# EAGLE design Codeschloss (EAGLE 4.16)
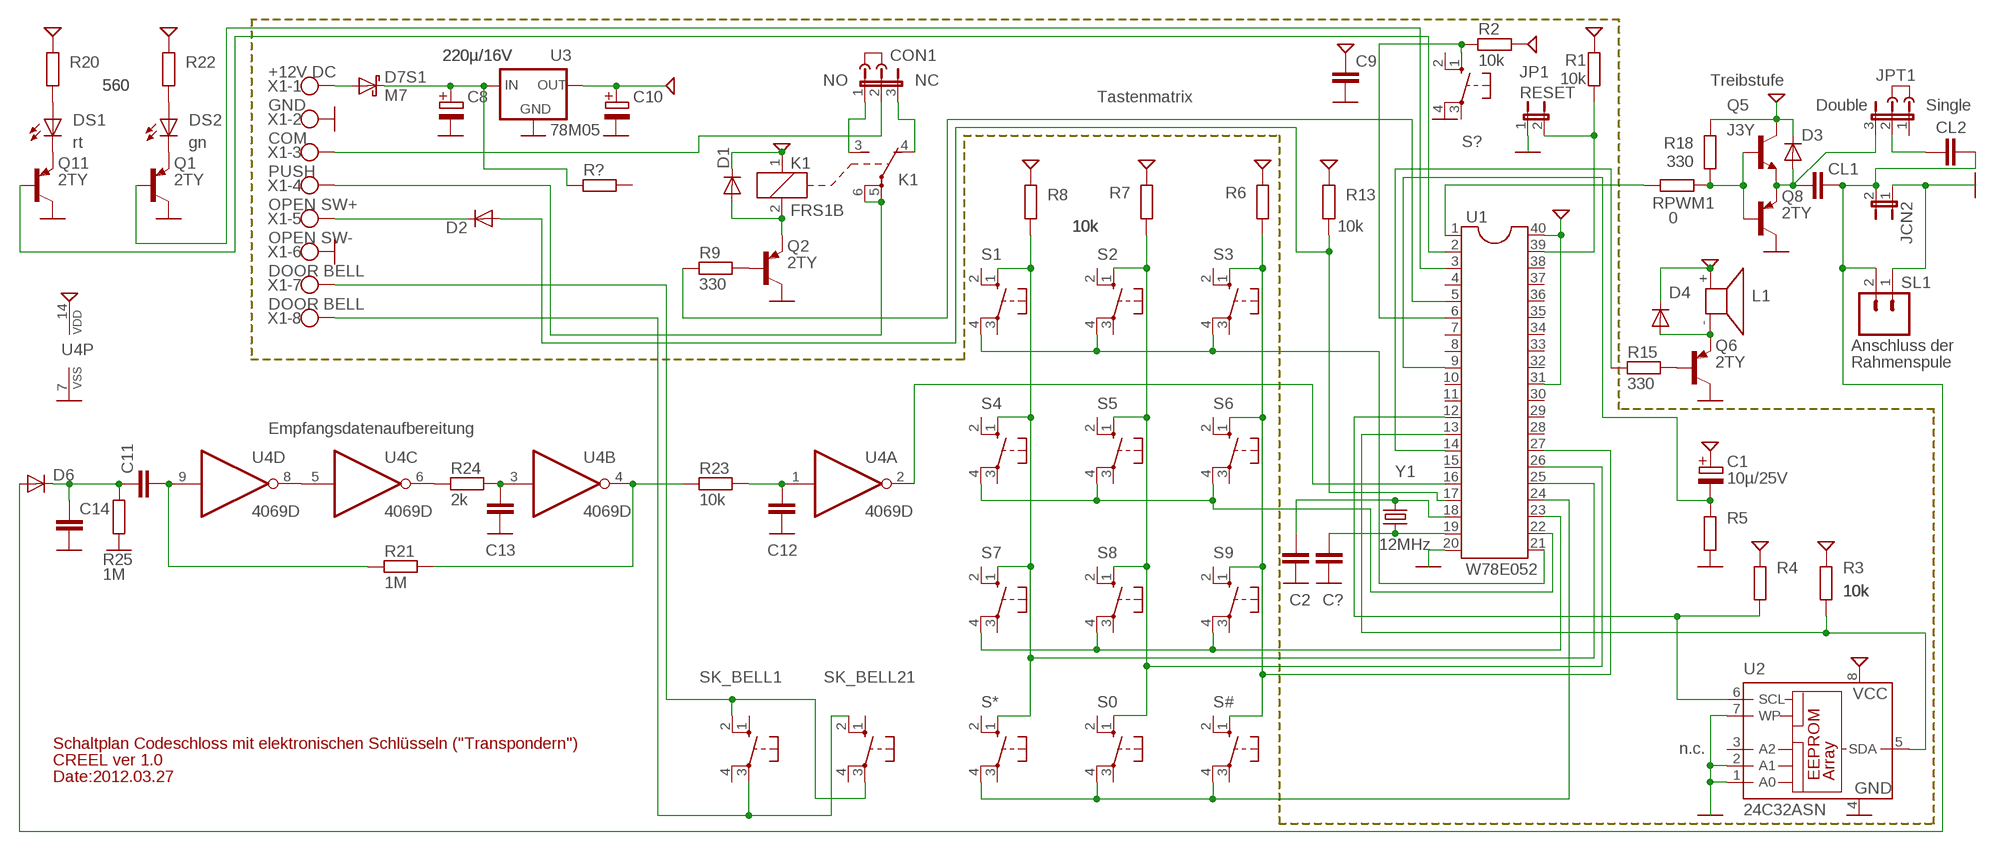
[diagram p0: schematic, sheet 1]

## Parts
C1  10µ/25V  E01-5  [E01-5]
C2  C0603  [0603]
C8  220µ/16V  E01-5  [E01-5]
C9  C0603  [0603]
C10  220µ/16V  E01-5  [E01-5]
C11  C0603  [0603]
C12  C0603  [0603]
C13  C0603  [0603]
C14  C0603  [0603]
C?  C0603  [0603]
CL1  C02  [C050-024X044]
CL2  C02  [C050-024X044]
CON1  JP2E  [JP2]
D1  D  [MINIMELF]
D2  D  [MINIMELF]
D3  D  [MINIMELF]
D4  D  [MINIMELF]
D6  D  [MINIMELF]
D7S1  M7  DSB  [SMB]
DS1  rt  LED3MM  [LED3MM]
DS2  gn  LED3MM  [LED3MM]
J1  JUMPER  [JUMP]
J2  JUMPER  [JUMP]
JCN2  JP1E  [JP1]
JP1  RESET  JP1E  [JP1]
JPT1  JP2E  [JP2]
K1  FRS1B  [FRS1B]
L1  KSS1201  [KSS1201]
Q1  2TY  PNP23BEC  [SOT23]
Q2  2TY  PNP23BEC  [SOT23]
Q5  J3Y  NPN23BEC  [SOT23]
Q6  2TY  PNP23BEC  [SOT23]
Q8  2TY  PNP23BEC  [SOT23]
Q11  2TY  PNP23BEC  [SOT23]
R1  10k  R0603  [0603]
R2  10k  R0603  [0603]
R3  10k  R0603  [0603]
R4  10k  R0603  [0603]
R5  10k  R0603  [0603]
R6  10k  R0603  [0603]
R7  10k  R0603  [0603]
R8  10k  R0603  [0603]
R9  330  R0603  [0603]
R13  10k  R0603  [0603]
R15  330  R0603  [0603]
R18  330  R0603  [0603]
R20  560  R0603  [0603]
R21  1M  R0603  [0603]
R22  560  R0603  [0603]
R23  10k  R0603  [0603]
R24  2k  R0603  [0603]
R25  1M  R0603  [0603]
R?  R0603  [0603]
RPWM1  0  R0603  [0603]
S0  10-XXSMD  [B3F-10SMD]
S1  10-XXSMD  [B3F-10SMD]
S2  10-XXSMD  [B3F-10SMD]
S3  10-XXSMD  [B3F-10SMD]
S4  10-XXSMD  [B3F-10SMD]
S5  10-XXSMD  [B3F-10SMD]
S6  10-XXSMD  [B3F-10SMD]
S7  10-XXSMD  [B3F-10SMD]
S8  10-XXSMD  [B3F-10SMD]
S9  10-XXSMD  [B3F-10SMD]
S#  10-XXSMD  [B3F-10SMD]
S*  10-XXSMD  [B3F-10SMD]
S?  10-XXSMD  [B3F-10SMD]
SK_BELL1  10-XXSMD  [B3F-10SMD]
SK_BELL21  10-XXSMD  [B3F-10SMD]
SL1  M02  [02P]
U1  W78E052  DIL40  [DIL40]
U2  24C32ASN  [SO-08]
U3  78M05  78MXXS  [78MXXS]
U4  4069D  [SO14]
X1  W237-08P  [W237-8P]
Y1  12MHz  CRYSTALS  [HC49/S]

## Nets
5P: C1.+ C9.1 C10.+ D1.K D3.K D4.K K1.1 L1.+ Q5.3(C) R1.2 R2.2 R3.2 R4.2 R6.2 R7.2 R8.2 R13.2 R18.2 R20.2 R22.2 U1.31 U1.40 U2.8(VCC) U3.OUT U4.14(P:VDD)
12P: C8.+ D7S1.1(K) R?.1 U3.IN
GND: C2.2 C8.- C9.2 C10.- C12.2 C13.2 C14.2 C?.2 JCN2.1 JP1.1 Q1.3(C) Q2.3(C) Q6.3(C) Q8.3(C) Q11.3(C) R5.1 R25.1 S?.4(P) SL1.1 U1.20 U2.1(A0) U2.2(A1) U2.4(GND) U2.7(WP) U3.GND U4.7(P:VSS) X1.2 X1.6
N$1: CL1.2 CL2.1 D6.A JCN2.2 SL1.2
N$2: CL2.2 JPT1.2
N$3: D7S1.2(A) X1.1
N$4: D1.A K1.2 Q2.2(E)
N$5: C?.1 U1.19 Y1.1
N$6: C2.1 U1.18 Y1.2
N$7: DS2.K(C) Q1.2(E)
N$8: DS1.K(C) Q11.2(E)
N$9: DS1.A R20.1
N$10: DS2.A R22.1
N$11: Q2.1(B) R9.2
N$12: R9.1 U1.5
N$13: S1.4(P) S2.4(P) S3.4(P) U1.21
N$14: R7.1 S0.1(S) S2.1(S) S5.1(S) S8.1(S) U1.26
N$15: R8.1 S1.1(S) S4.1(S) S7.1(S) S*.1(S) U1.25
N$16: R3.1 U1.13 U2.5(SDA)
N$17: R4.1 U1.12 U2.6(SCL)
N$18: S4.4(P) S5.4(P) S6.4(P) U1.22
N$19: Q11.1(B) U1.2
N$20: SK_BELL1.3(P) SK_BELL21.2(S) X1.8
N$21: Q1.1(B) U1.3
N$22: R6.1 S3.1(S) S6.1(S) S9.1(S) S#.1(S) U1.27
N$23: JP1.2 R1.1 U1.39
N$24: D4.A L1.- Q6.2(E)
N$25: S7.4(P) S8.4(P) S9.4(P) U1.23
N$26: S0.4(P) S#.4(P) S*.4(P) U1.24
N$27: Q6.1(B) R15.2
N$28: SK_BELL1.2(S) SK_BELL21.3(P) X1.7
N$29: R15.1 U1.14
N$30: D2.A R13.1 U1.17
N$31: RPWM1.1 U1.1
N$32: Q5.1(B) Q8.1(B) R18.1 RPWM1.2
N$33: CL1.1 D3.A JPT1.3 Q5.2(E) Q8.2(E)
N$34: C11.1 C14.1 D6.K R25.2
N$35: C11.2 R21.1 U4.9(D:I)
N$36: R21.2 R23.1 U4.4(B:O)
N$37: C12.1 R23.2 U4.1(A:I)
N$38: C13.1 R24.2 U4.3(B:I)
N$39: R24.1 U4.6(C:O)
N$40: U1.16 U4.2(A:O)
N$41: U4.5(C:I) U4.8(D:O)
N$42: CON1.1 K1.3(2:S)
N$43: CON1.3 K1.4(2:O)
N$44: K1.5(2:P) K1.6(2:P) X1.4
N$45: D2.K X1.5
N$46: CON1.2 X1.3
N$48: R2.1 S?.1(S) U1.6
RESET: C1.- R5.2 U1.9
Unconnected: JPT1.1 R?.2 S0.2(S) S0.3(P) S1.2(S) S1.3(P) S2.2(S) S2.3(P) S3.2(S) S3.3(P) S4.2(S) S4.3(P) S5.2(S) S5.3(P) S6.2(S) S6.3(P) S7.2(S) S7.3(P) S8.2(S) S8.3(P) S9.2(S) S9.3(P) S#.2(S) S#.3(P) S*.2(S) S*.3(P) S?.2(S) S?.3(P) SK_BELL1.1(S) SK_BELL1.4(P) SK_BELL21.1(S) SK_BELL21.4(P) U1.4 U1.7 U1.8 U1.10 U1.11 U1.15 U1.28 U1.29 U1.30 U1.32 U1.33 U1.34 U1.35 U1.36 U1.37 U1.38 U2.3(A2) U4.10(E:O) U4.11(E:I) U4.12(F:O) U4.13(F:I)

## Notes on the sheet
- +12V DC
- NO | NC | Treibstufe
- Tastenmatrix
- GND | Double | Single
- COM
- PUSH
- OPEN SW+
- OPEN SW-
- DOOR BELL
- DOOR BELL
- Anschluss der
- Rahmenspule
- Empfangsdatenaufbereitung
- Schaltplan Codeschloss mit elektronischen Schlüsseln ("Transpondern")
- n.c.
- CREEL ver 1.0
- Date:2012.03.27

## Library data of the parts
C1 C8 C10 = Ofen:E: Elektrolytkondensator
C2 C9 C11-C14 C? CL1 CL2 = Ofen:C: Kondensator
CON1 JPT1 = jumper:JP2E: JUMPER
D1-D4 D6 = Ofen:D: Diode
D7S1 = Ofen:DS: Schottky-Diode
DS1 DS2 = led:LED: LED
J1 J2 = jumper:JUMPER: JUMPER header
JCN2 JP1 = jumper:JP1E: JUMPER
K1 = Ofen:FRS1B: Relais, 1 Umschaltkontakt
L1 = buzzer:KSS1201: SPEAKER
Q1 Q2 Q6 Q8 Q11 = Ofen:PNP: PNP-Transistor Verschiedene Bauformen und Leistungen
Q5 = Ofen:NPN: NPN-Transistor Verschiedene Bauformen und Leistungen
R1-R9 R13 R15 R18 R20-R25 R? RPWM1 = Ofen:R: Widerstand
S0 S1-S9 S# S* S? SK_BELL1 SK_BELL21 = Ofen:10-XX: Drucktaster
SL1 = con-amp-quick:M02: AMP QUICK CONNECTOR
U1 = ic-package:DIL40: Dual In Line
U2 = microchip:24*: Serial EEPROM I2C
U3 = v-reg:78MXXS: VOLTAGE REGULATOR
U4 = 40xx:4069: Hex INVERTER
X1 = con-wago-508:W237-08P: WAGO SREW CLAMP
Y1 = Ofen:CRYSTAL: Quarz

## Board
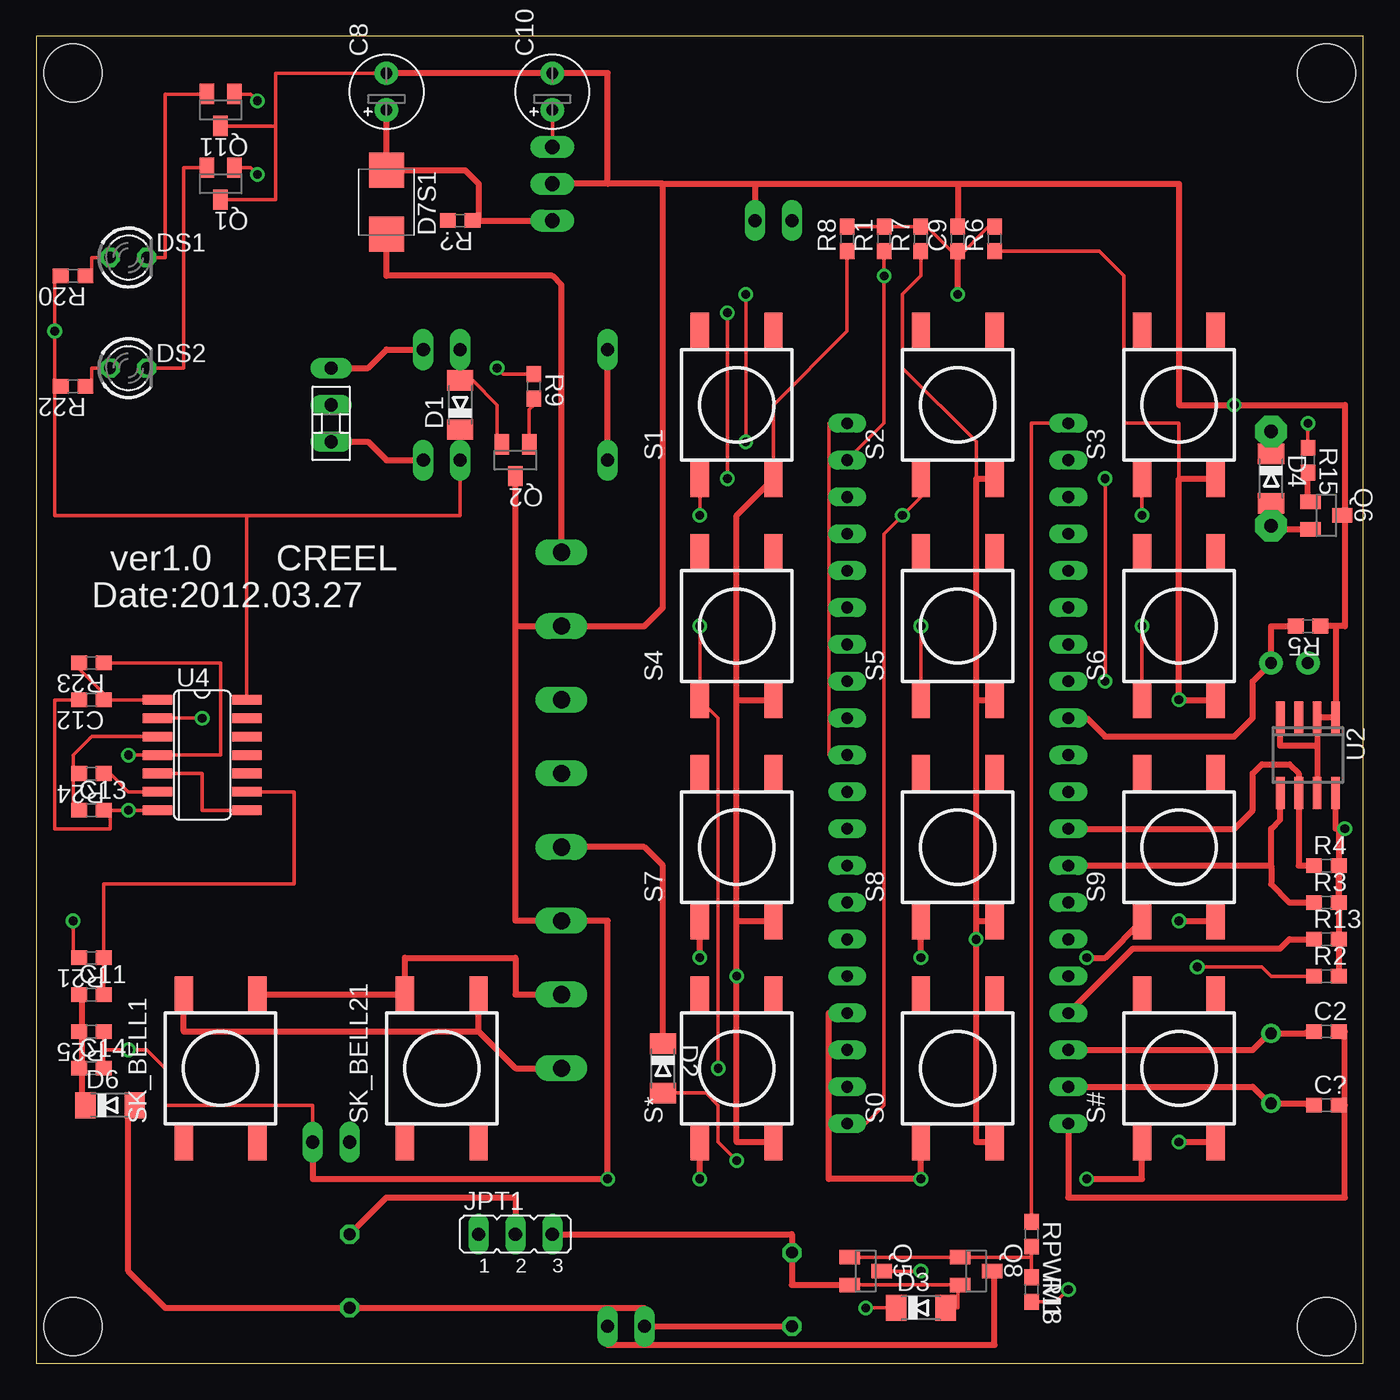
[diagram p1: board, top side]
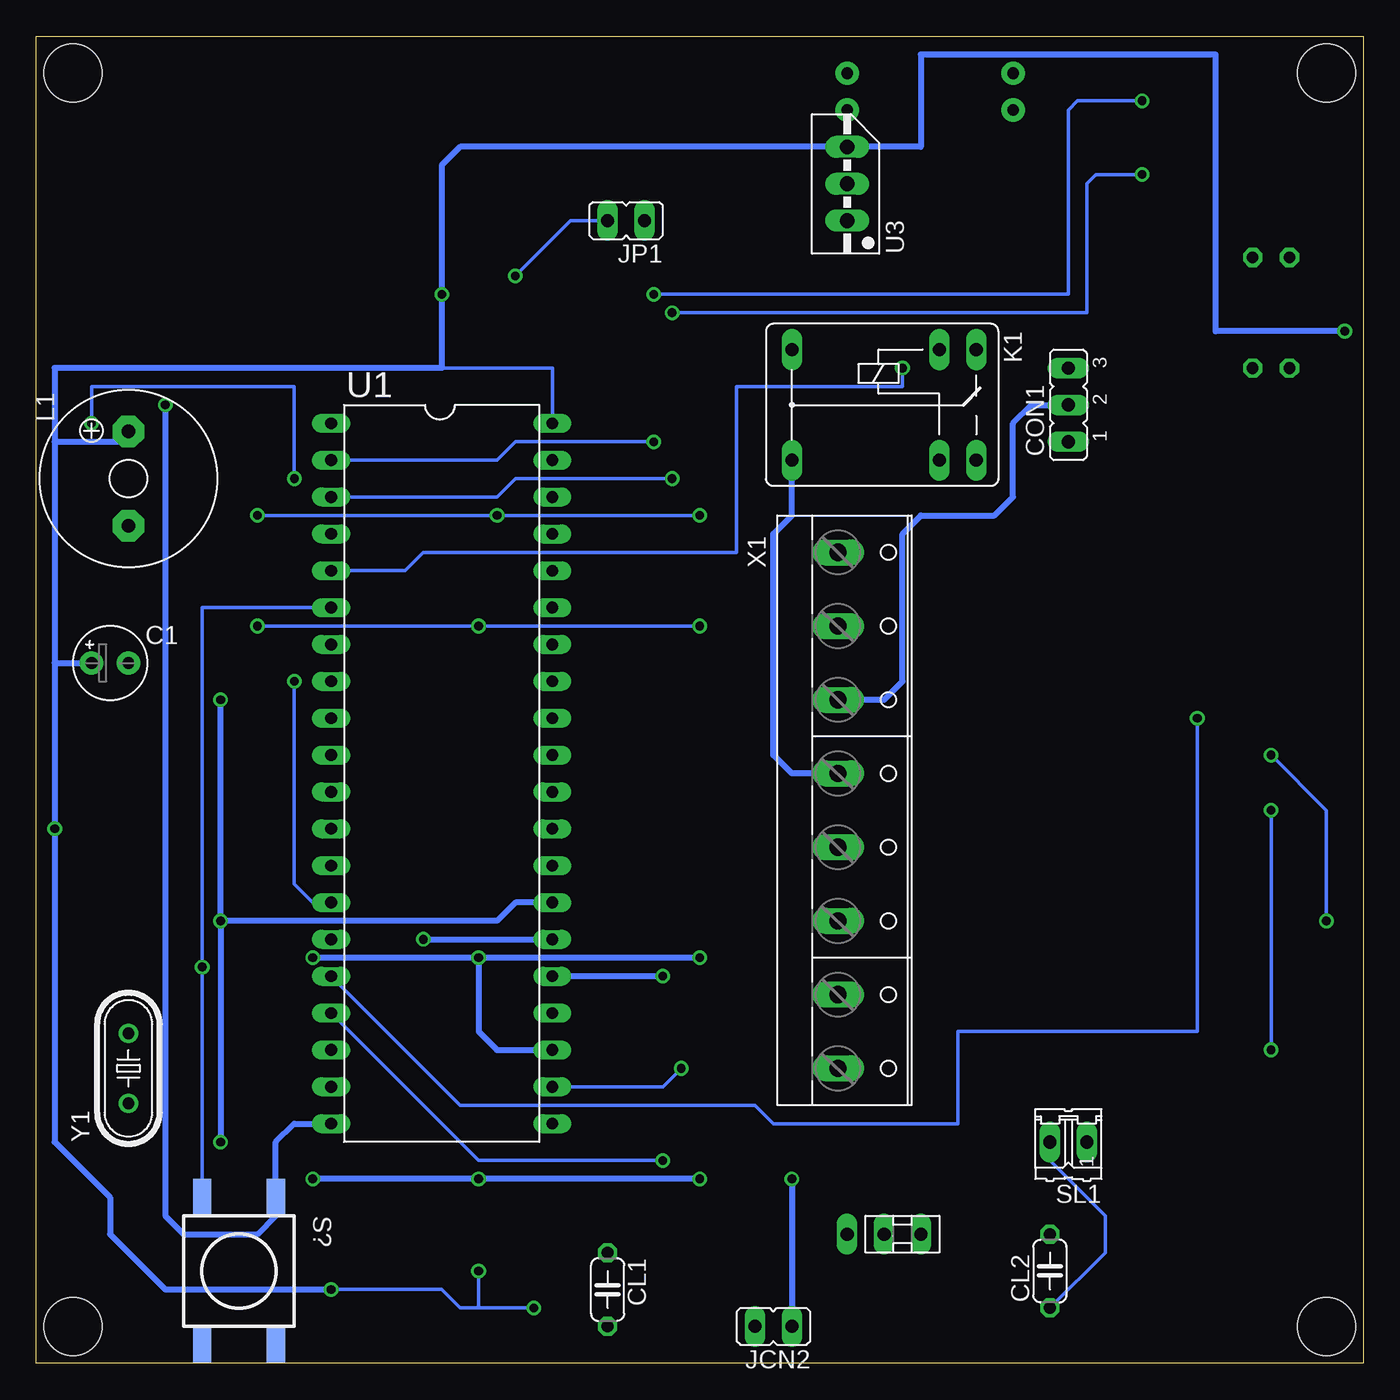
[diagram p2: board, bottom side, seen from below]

Size 91.44 x 91.44 mm. Coordinates in mm from the lower left corner, seen from the top.
Outline: 0,0 91.44,0 91.44,91.44 0,91.44 0,0
Copper layers (1+16): Top 0.035mm / dielectric 1mm / Bottom 0.035mm
Design rules "default": minimum track width 10mil, minimum drill 0.6mm, track to track 8mil, track to pad 8mil, pad to pad 8mil, via to via 8mil, smd to smd 0mil, copper to edge 0mil, drill to drill 8mil, minimum pad ring 10mil, minimum via ring 8mil, stop-mask expansion 4mil, vias tented up to drill 0mil, thermal gap 10mil
Holes 4 mm at 2.54,2.54 88.9,2.54 88.9,88.9 2.54,88.9

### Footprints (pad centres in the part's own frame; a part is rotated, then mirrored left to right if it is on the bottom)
E01-5 = drill 0.813 pad 1.6 round: + -1.27,0; - 1.27,0
0603 = smd 1.1 x 1: 1 -0.85,0; 2 0.85,0
C050-024X044 = drill 0.813 octagon: 1 -2.54,0; 2 2.54,0
JP2 = drill 0.914 long: 1 -2.54,0; 2 0,0; 3 2.54,0
MINIMELF = smd 1.4 x 1.8: A 1.7,0; K -1.7,0
SMB = smd 2.4 x 2.4: 1 -2.2,0; 2 2.2,0
LED3MM = drill 0.813 octagon: A -1.27,0; K 1.27,0
JP1 = drill 0.914 long: 1 0,-1.27; 2 0,1.27
FRS1B = drill 0.914 long: 1 0,3.81; 2 0,-3.81; 3 -2.54,3.81; 4 -2.54,-3.81; 5 10.16,3.81; 6 10.16,-3.81
KSS1201 = drill 0.914 pad 2.159 octagon: + 3.251,0; - -3.251,0
SOT23 = smd 1 x 1.4: 1 -0.95,-1.1; 2 0.95,-1.1; 3 0,1.1
B3F-10SMD = smd 2.54 x 1.27: 1 -5.08,-2.54; 2 5.08,-2.54; 3 5.08,2.54; 4 -5.08,2.54
02P = drill 0.914 long: 1 -1.27,0; 2 1.27,0
DIL40 = drill 0.813 long: 1 -24.13,-7.62; 2 -21.59,-7.62; 3 -19.05,-7.62; 4 -16.51,-7.62; 5 -13.97,-7.62; 6 -11.43,-7.62; 7 -8.89,-7.62; 8 -6.35,-7.62; 9 -3.81,-7.62; 10 -1.27,-7.62; 11 1.27,-7.62; 12 3.81,-7.62; 13 6.35,-7.62; 14 8.89,-7.62; 15 11.43,-7.62; 16 13.97,-7.62; 17 16.51,-7.62; 18 19.05,-7.62; 19 21.59,-7.62; 20 24.13,-7.62; 21 24.13,7.62; 22 21.59,7.62; 23 19.05,7.62; 24 16.51,7.62; 25 13.97,7.62; 26 11.43,7.62; 27 8.89,7.62; 28 6.35,7.62; 29 3.81,7.62; 30 1.27,7.62; 31 -1.27,7.62; 32 -3.81,7.62; 33 -6.35,7.62; 34 -8.89,7.62; 35 -11.43,7.62; 36 -13.97,7.62; 37 -16.51,7.62; 38 -19.05,7.62; 39 -21.59,7.62; 40 -24.13,7.62
SO-08 = smd 0.6 x 2.2: 1 -1.905,-2.6; 2 -0.635,-2.6; 3 0.635,-2.6; 4 1.905,-2.6; 5 1.905,2.6; 6 0.635,2.6; 7 -0.635,2.6; 8 -1.905,2.6
78MXXS = drill 1.016 long: GND 0,-2.54; IN -2.54,-2.54; OUT 2.54,-2.54
SO14 = smd 0.66 x 2.032: 1 -3.81,-3.073; 2 -2.54,-3.073; 3 -1.27,-3.073; 4 0,-3.073; 5 1.27,-3.073; 6 2.54,-3.073; 7 3.81,-3.073; 8 3.81,3.073; 9 2.54,3.073; 10 1.27,3.073; 11 0,3.073; 12 -1.27,3.073; 13 -2.54,3.073; 14 -3.81,3.073
W237-8P = drill 1.194 long: 1 -17.78,-0.635; 2 -12.7,-0.635; 3 -7.62,-0.635; 4 -2.54,-0.635; 5 2.54,-0.635; 6 7.62,-0.635; 7 12.7,-0.635; 8 17.78,-0.635
HC49/S = drill 0.813 round: 1 -2.413,0; 2 2.413,0

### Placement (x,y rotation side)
C1  86.36,48.26 0 bottom
C2  88.9,22.86 0 top
C8  24.13,87.63 90 top
C9  63.5,77.47 90 top
C10  35.56,87.63 90 top
C11  3.81,25.4 0 top
C12  3.81,45.72 180 top
C13  3.81,38.1 0 top
C14  3.81,20.32 0 top
C?  88.9,17.78 0 top
CL1  52.07,5.08 270 bottom
CL2  21.59,6.35 90 bottom
CON1  20.32,66.04 90 bottom
D1  29.21,66.04 90 top
D2  43.18,20.32 270 top
D3  60.96,3.81 0 top
D4  85.09,60.96 270 top
D6  5.08,17.78 0 top
D7S1  24.13,80.01 270 top
DS1  6.35,76.2 0 top
DS2  6.35,68.58 0 top
J1  20.32,64.77 0 top
J2  31.75,8.89 90 bottom
JCN2  40.64,2.54 90 bottom
JP1  50.8,78.74 90 bottom
JPT1  33.02,8.89 0 top
K1  29.21,66.04 180 bottom
L1  85.09,60.96 90 bottom
Q1  12.7,81.28 180 top
Q2  33.02,62.23 180 top
Q5  57.15,6.35 270 top
Q6  88.9,58.42 270 top
Q8  64.77,6.35 270 top
Q11  12.7,86.36 180 top
R1  58.42,77.47 90 top
R2  88.9,26.67 0 top
R3  88.9,31.75 0 top
R4  88.9,34.29 0 top
R5  87.63,50.8 180 top
R6  66.04,77.47 90 top
R7  60.96,77.47 90 top
R8  55.88,77.47 90 top
R9  34.29,67.31 270 top
R13  88.9,29.21 0 top
R15  87.63,62.23 270 top
R18  68.58,5.08 270 top
R20  2.54,74.93 180 top
R21  3.81,27.94 180 top
R22  2.54,67.31 180 top
R23  3.81,48.26 180 top
R24  3.81,40.64 180 top
R25  3.81,22.86 180 top
R?  29.21,78.74 180 top
RPWM1  68.58,8.89 270 top
S0  63.5,20.32 90 top
S1  48.26,66.04 90 top
S2  63.5,66.04 90 top
S3  78.74,66.04 90 top
S4  48.26,50.8 90 top
S5  63.5,50.8 90 top
S6  78.74,50.8 90 top
S7  48.26,35.56 90 top
S8  63.5,35.56 90 top
S9  78.74,35.56 90 top
S#  78.74,20.32 90 top
S*  48.26,20.32 90 top
S?  77.47,6.35 270 bottom
SK_BELL1  12.7,20.32 90 top
SK_BELL21  27.94,20.32 90 top
SL1  20.32,15.24 180 bottom
U1  63.5,40.64 270 bottom
U2  87.63,41.91 180 top
U3  38.1,81.28 90 bottom
U4  11.43,41.91 270 top
X1  35.56,38.1 270 bottom
Y1  85.09,20.32 90 bottom

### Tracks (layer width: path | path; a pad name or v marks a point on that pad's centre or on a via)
5P  (via drill 0.6)
  Top 0.254: R20.2 1.27,74.93 v1.27,71.12 1.27,67.31 | 1.27,67.31 R22.2 | 1.27,67.31 1.27,58.42 14.61,58.42 | 14.61,58.42 29.21,58.42 K1.1 D1.K 29.21,64.77 | R1.2 R8.2 | R1.2 R7.2 61.38,78.32 63.5,76.2 65.62,78.32 R6.2 | R1.2 58.42,78.74 | v60.96,6.35 Q5.3 | 59.69,3.81 D3.K v57.15,3.81 | R18.2 70.27,4.23 v71.12,5.08 | U4.14 14.5,58.42 14.61,58.42 | U1.40 54.61,64.77 54.61,41.91 U1.31 | U3.OUT C10.+
  Top 0.406: C9.1 63.5,76.2 v63.5,73.66 | 89.53,39.37 U2.8 89.53,36.83 v90.17,36.83 89.75,36.83 R3.2 R4.2 R13.2 R2.2 | L1.+ D4.K
  Bottom 0.254: 60.96,3.81 v60.96,6.35 | 60.96,3.81 v57.15,3.81 | 60.96,3.81 62.23,3.81 63.5,5.08 v71.12,5.08 | 63.5,68.58 55.88,68.58 U1.40
  Bottom 0.406: v1.27,71.12 10.16,71.12 10.16,90.17 30.48,90.17 30.48,83.82 U3.OUT 62.23,83.82 63.5,82.55 v63.5,73.66 63.5,68.58 90.17,68.58 90.17,63.5 | 90.17,63.5 90.17,48.26 | 90.17,48.26 v90.17,36.83 90.17,15.24 86.36,11.43 86.36,8.89 82.55,5.08 v71.12,5.08 | 90.17,48.26 C1.+ | L1.+ 85.09,63.5 90.17,63.5
12P
  Top 0.406: 30.48,78.74 U3.IN | C8.+ D7S1.1 29.55,82.21 30.48,81.28 30.48,78.74 | 30.48,78.74 R?.1
GND  (via drill 0.6)
  Top 0.254: 16.51,85.26 Q11.3 | 16.51,85.26 16.51,88.9 C8.- | Q1.3 16.51,80.18 16.51,85.26 | C14.2 R25.1 | C14.2 5.08,20.32 | C14.2 4.66,21.59 v6.35,21.59 7.62,21.59 8.89,20.32 8.89,17.78 19.05,17.78 SL1.1 | U4.7 v6.35,38.1 5.08,38.1 | C12.2 1.27,45.72 1.27,36.83 5.08,36.83 5.08,38.1 | 5.08,38.1 C13.2
  Top 0.406: C8.- C10.- 39.37,88.9 39.37,81.28 | 39.37,81.28 U3.GND | 43.18,81.28 49.53,81.28 | 43.18,81.28 39.37,81.28 | 49.53,81.28 JP1.1 | 63.5,81.28 C9.2 | 63.5,81.28 78.74,81.28 78.74,66.04 v82.55,66.04 90.17,66.04 90.17,58.42 | 90.17,17.78 C?.2 | C2.2 90.17,22.86 90.17,17.78 | 90.17,17.78 90.17,11.43 71.12,11.43 U1.20 | Q8.3 66.04,6.35 66.04,1.27 39.37,1.27 JCN2.1 | SL1.1 19.05,12.7 v39.37,12.7 39.37,30.48 X1.6 33.02,30.48 33.02,50.8 | 33.02,50.8 Q2.3 | 33.02,50.8 X1.2 41.91,50.8 43.18,52.07 43.18,81.28 | U2.1 U2.2 88.27,42.55 | U2.1 89.53,44.45 | 88.27,42.55 U2.7 | U2.4 85.72,42.55 88.27,42.55 | 89.53,50.8 U2.1 | 89.53,50.8 R5.1 | 89.53,50.8 90.17,50.8 90.17,58.42 | 90.17,58.42 Q6.3 | 49.53,81.28 63.5,81.28
  Bottom 0.254: v6.35,21.59 v6.35,38.1
  Bottom 0.406: U1.20 73.66,16.51 74.93,15.24 S?.4 74.93,10.16 76.2,8.89 81.28,8.89 82.55,10.16 v82.55,66.04 | v39.37,12.7 JCN2.1
N$1
  Top 0.406: CL1.2 JCN2.2 41.91,3.81 CL2.1 8.89,3.81 6.35,6.35 6.35,17.78 D6.A
  Bottom 0.254: SL1.2 21.59,13.97 17.78,10.16 17.78,7.62 CL2.1
N$2
  Top 0.406: JPT1.2 33.02,11.43 24.13,11.43 CL2.2
N$3
  Top 0.406: X1.1 36.2,74.3 35.56,74.93 24.13,74.93 D7S1.2
N$4
  Top 0.254: K1.2 D1.A 30.05,67.74 31.75,66.04 31.75,63.5 31.92,63.33 Q2.2
N$5
  Top 0.406: U1.19 83.82,19.05 85.09,17.78 Y1.1 87.5,17.91 87.63,17.78 C?.1
N$6
  Top 0.406: U1.18 83.82,21.59 85.09,22.86 Y1.2 87.5,22.73 87.63,22.86 C2.1
N$7
  Top 0.254: Q1.2 10.16,82.38 10.16,68.58 DS2.K
N$8
  Top 0.254: Q11.2 8.89,87.46 8.89,76.2 DS1.K
N$9
  Top 0.254: R20.1 3.81,74.93 3.81,76.2 DS1.A
N$10
  Top 0.254: R22.1 3.81,67.31 3.81,68.58 DS2.A
N$11
  Top 0.254: R9.2 34.29,66.04 33.97,65.72 Q2.1
N$12  (via drill 0.6)
  Top 0.254: R9.1 32.17,68.16 v31.75,68.58
  Bottom 0.254: v31.75,68.58 31.75,67.31 43.18,67.31 43.18,55.88 64.77,55.88 66.04,54.61 U1.5
N$13  (via drill 0.6)
  Top 0.254: v45.72,58.42 S1.4 | S2.4 60.96,59.69 v59.69,58.42 58.42,57.15 58.42,17.78 57.15,16.51 U1.21 | v76.2,58.42 S3.4
  Bottom 0.254: v45.72,58.42 v59.69,58.42 v76.2,58.42
N$14  (via drill 0.6)
  Top 0.254: R7.1 60.96,74.93 59.69,73.66 59.69,68.58 64.77,63.5 64.77,60.96
  Top 0.406: S2.1 64.77,60.96 64.77,45.72 | 64.77,45.72 S5.1 | 64.77,30.48 S8.1 | 64.77,30.48 64.77,45.72 | S0.1 64.77,15.24 v64.77,29.21 64.77,30.48
  Bottom 0.406: v64.77,29.21 U1.26
N$15  (via drill 0.6)
  Top 0.254: S1.1 50.8,66.04 55.88,71.12 R8.1
  Top 0.406: 48.26,45.72 48.26,58.42 S1.1 | 48.26,45.72 S4.1 | 48.26,30.48 S7.1 | 48.26,30.48 48.26,45.72 | S*.1 48.26,15.24 v48.26,26.67 48.26,30.48
  Bottom 0.406: v48.26,26.67 U1.25
N$16
  Top 0.406: U2.5 85.72,37.47 85.09,36.83 85.09,34.29 | 85.09,34.29 85.09,33.02 86.36,31.75 R3.1 | U1.13 85.09,34.29
N$17
  Top 0.406: U1.12 82.55,36.83 83.82,38.1 83.82,40.64 84.45,41.27 86.36,41.27 87,40.64 U2.6 87,34.29 R4.1
N$18  (via drill 0.6)
  Top 0.254: v45.72,50.8 S4.4 46.99,44.45 v46.99,20.32 | v60.96,50.8 S5.4 | v76.2,50.8 S6.4
  Bottom 0.254: v45.72,50.8 v60.96,50.8 v76.2,50.8 | v46.99,20.32 48.26,19.05 U1.22
N$19  (via drill 0.6)
  Top 0.254: Q11.1 14.78,87.46 v15.24,87 | v48.9,73.66 v48.9,63.5
  Bottom 0.254: v15.24,87 19.68,87 20.32,86.36 20.32,73.66 v48.9,73.66 | v48.9,63.5 58.42,63.5 59.69,62.23 U1.2
N$20
  Top 0.406: SK_BELL1.3 10.16,22.86 30.48,22.86 | 30.48,22.86 SK_BELL21.2 | X1.8 33.02,20.32 30.48,22.86
N$21  (via drill 0.6)
  Top 0.254: Q1.1 14.78,82.38 v15.24,81.92 | v47.62,72.39 v47.62,60.96
  Bottom 0.254: v15.24,81.92 18.41,81.92 19.05,81.28 19.05,72.39 v47.62,72.39 | v47.62,60.96 58.42,60.96 59.69,59.69 U1.3
N$22  (via drill 0.6)
  Top 0.254: R6.1 73.24,76.62 74.93,74.93 74.93,64.77 78.74,64.77 78.74,60.96
  Top 0.406: S3.1 78.74,60.96 v78.74,45.72 S6.1 | v78.74,30.48 S9.1 | v78.74,15.24 S#.1
  Bottom 0.406: v78.74,30.48 v78.74,45.72 | v78.74,30.48 v78.74,15.24 | v78.74,30.48 59.69,30.48 58.42,31.75 U1.27
N$23  (via drill 0.6)
  Top 0.254: U1.39 58.42,64.77 v58.42,74.93 R1.1
  Bottom 0.254: JP1.2 54.61,78.74 v58.42,74.93
N$24
  Top 0.406: 85.09,57.78 D4.A | L1.- 85.09,57.78 | Q6.2 85.09,57.47 85.09,57.78
N$25  (via drill 0.6)
  Top 0.406: S9.4 73.66,27.94 v72.39,27.94 | v60.96,27.94 S8.4 | v45.72,27.94 S7.4
  Bottom 0.406: v60.96,27.94 v72.39,27.94 | v45.72,27.94 v60.96,27.94 | U1.23 59.69,21.59 60.96,22.86 v60.96,27.94
N$26  (via drill 0.6)
  Top 0.406: S0.4 v60.96,12.7 54.61,12.7 54.61,24.13 U1.24 | v45.72,12.7 S*.4 | S#.4 76.2,12.7 v72.39,12.7
  Bottom 0.406: v45.72,12.7 v60.96,12.7 v72.39,12.7
N$27
  Top 0.406: Q6.1 87.63,59.37 R15.2
N$28
  Top 0.406: X1.7 33.02,25.4 33.02,27.94 25.4,27.94 SK_BELL21.3 SK_BELL1.2
N$29  (via drill 0.6)
  Top 0.254: v87.63,64.77 R15.1 | v73.66,46.99 v73.66,60.96
  Bottom 0.254: v87.63,64.77 87.63,67.31 73.66,67.31 v73.66,60.96 | v73.66,46.99 73.66,33.02 72.39,31.75 U1.14
N$30  (via drill 0.6)
  Top 0.254: D2.A 46.15,18.62 46.99,17.78 46.99,15.24 v48.26,13.97
  Top 0.406: U1.17 75.56,28.57 85.72,28.57 86.36,29.21 R13.1
  Bottom 0.254: v48.26,13.97 60.96,13.97 U1.17
N$31
  Top 0.254: U1.1 68.58,64.77 RPWM1.1
N$32
  Top 0.254: Q5.1 Q8.1 68.58,7.3 68.58,7.62 | 68.58,7.62 R18.1 | 68.58,7.62 RPWM1.2
N$33
  Top 0.254: Q5.2 63.5,5.4 | 63.5,5.4 Q8.2 | D3.A 63.5,3.81 63.5,5.4
  Top 0.406: Q5.2 52.07,5.4 CL1.1 52.07,8.89 JPT1.3
N$34
  Top 0.406: D6.K 3.17,17.78 3.17,20.32 | 3.17,20.32 C14.1 | 3.17,20.32 3.17,22.86 | 3.17,22.86 R25.2 | C11.1 3.17,25.4 3.17,22.86
N$35
  Top 0.254: C11.2 R21.1 | R21.1 5.08,27.94 | R21.1 4.66,33.02 17.78,33.02 17.78,39.37 U4.9
N$36  (via drill 0.6)
  Top 0.254: R23.1 12.7,48.26 12.7,41.91 U4.4 | U4.4 8.26,41.91 | v6.35,41.91 U4.4 | R21.2 2.54,27.94 v2.54,30.48
  Bottom 0.254: v6.35,41.91 2.54,38.1 v2.54,30.48
N$37
  Top 0.254: C12.1 5.08,45.72 | R23.2 2.96,47.84 5.08,45.72 | 5.08,45.72 8.26,45.72 | U4.1 8.89,45.72 | 8.26,45.72 U4.1 | 8.26,45.72 U4.1
N$38
  Top 0.254: U4.3 3.81,43.18 2.54,41.91 2.54,40.64 | C13.1 2.54,38.1 2.54,40.64 | 2.54,40.64 R24.2
N$39
  Top 0.254: R24.1 5.08,40.64 6.35,39.37 U4.6
N$40  (via drill 0.6)
  Top 0.254: v11.43,44.45 U4.2
  Bottom 0.254: v11.43,44.45 11.43,22.86 27.94,22.86 27.94,16.51 40.64,16.51 41.91,17.78 62.23,17.78 U1.16
N$41
  Top 0.254: U4.5 11.43,40.64 11.43,38.1 U4.8 14.61,38.1
N$42
  Top 0.406: K1.3 24.13,62.23 22.86,63.5 CON1.1
N$43
  Top 0.406: K1.4 24.13,69.85 22.86,68.58 CON1.3
N$44
  Top 0.406: K1.5 K1.6
  Bottom 0.406: K1.5 39.37,58.42 40.64,57.15 40.64,41.91 39.37,40.64 X1.4
N$45
  Top 0.406: X1.5 41.91,35.56 43.18,34.29 D2.K 43.18,21.59
N$46
  Bottom 0.406: X1.3 33.02,45.72 31.75,46.99 31.75,57.15 30.48,58.42 25.4,58.42 24.13,59.69 24.13,64.77 22.86,66.04 CON1.2
N$48  (via drill 0.6)
  Top 0.254: R2.1 85.09,26.67 84.45,27.3 v80.01,27.3
  Bottom 0.254: U1.6 80.01,52.07 v80.01,27.3 S?.1
RESET
  Top 0.406: U1.9 72.39,44.45 73.66,43.18 82.55,43.18 83.82,44.45 83.82,46.99 C1.- 85.09,50.8 R5.2

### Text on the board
tPlace: ver1.0 | CREEL | Date:2012.03.27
